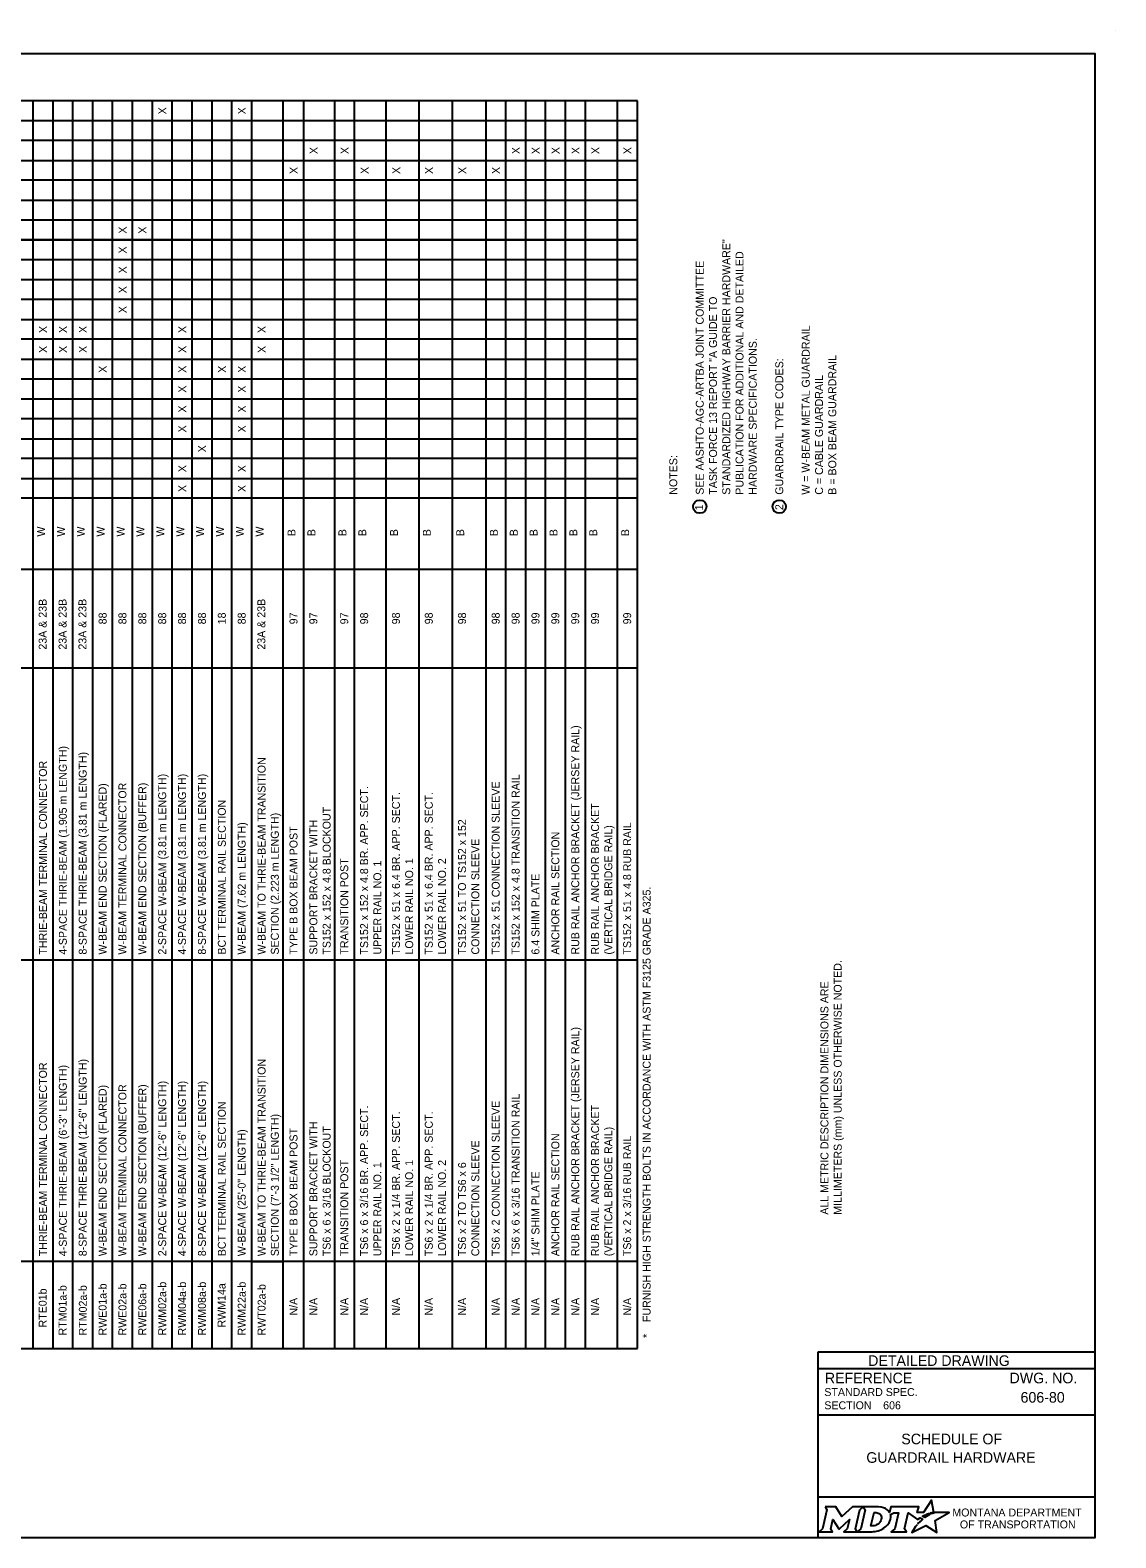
# Model space of a CAD drawing. Extents: x 49991.4 to 50021, y 49987.6 to 50011.4.
# Drawn here: x 50008.71 to 50016.9, y 49987.8 to 49999.18 of the extents above; entities that cross this region are included whole.
import ezdxf

# ---------------------------------------------------------------- set-up
doc = ezdxf.new("R2010")
doc.units = 0
for name, color, linetype in [('Default', 7, 'Continuous'), ('Level 1', 7, 'Continuous'), ('Level 2', 7, 'Continuous'), ('Level 5', 7, 'Continuous')]:
    doc.layers.add(name, color=color, linetype=linetype)

msp = doc.modelspace()

# ---------------------------------------------------------------- linework, layer by layer
at = {"layer": 'Default'}
for points in [[(50015.513, 49987.981), (50015.502, 49987.987), (50015.514, 49987.99), (50015.526, 49987.991), (50015.508, 49988.082), (50015.449, 49987.99), (50015.401, 49987.99), (50015.412, 49988.034), (50015.202, 49988.034), (50015.192, 49987.991), (50015.186, 49988)], [(50014.706, 49988.034), (50014.72, 49988.01), (50014.686, 49987.867), (50014.66, 49987.845), (50014.762, 49987.845), (50014.749, 49987.867), (50014.765, 49987.937), (50014.809, 49987.868), (50014.814, 49987.868), (50014.889, 49987.938), (50014.872, 49987.867), (50014.848, 49987.845), (50014.949, 49987.845), (50014.936, 49987.868), (50014.969, 49988.011)], [(50014.969, 49988.011), (50014.994, 49988.034), (50014.912, 49988.034), (50014.832, 49987.961), (50014.788, 49988.034), (50014.706, 49988.034)], [(50015.108, 49988.034), (50014.994, 49988.034), (50015.009, 49988.011), (50014.975, 49987.867), (50014.949, 49987.845), (50015.06, 49987.845)], [(50015.132, 49987.947), (50015.13, 49987.939), (50015.127, 49987.93), (50015.123, 49987.922), (50015.118, 49987.914), (50015.111, 49987.907), (50015.103, 49987.901), (50015.095, 49987.896), (50015.086, 49987.892), (50015.077, 49987.89), (50015.067, 49987.889), (50015.052, 49987.889), (50015.075, 49987.989), (50015.091, 49987.989), (50015.099, 49987.988), (50015.106, 49987.986), (50015.113, 49987.983), (50015.119, 49987.979), (50015.124, 49987.974), (50015.128, 49987.968), (50015.13, 49987.962), (50015.132, 49987.955), (50015.132, 49987.952), (50015.132, 49987.947)], [(50015.199, 49987.975), (50015.224, 49987.988), (50015.261, 49987.988), (50015.232, 49987.867), (50015.205, 49987.845), (50015.321, 49987.845), (50015.304, 49987.867), (50015.332, 49987.988), (50015.403, 49987.936), (50015.424, 49987.951), (50015.444, 49987.94)], [(50015.388, 49987.884), (50015.373, 49987.86), (50015.368, 49987.852), (50015.362, 49987.844), (50015.36, 49987.839), (50015.465, 49987.893), (50015.549, 49987.838), (50015.536, 49987.93), (50015.643, 49987.989), (50015.594, 49987.989), (50015.564, 49987.99), (50015.543, 49987.99), (50015.536, 49987.989), (50015.531, 49987.987), (50015.523, 49987.985), (50015.513, 49987.981)], [(50015.462, 49987.954), (50015.46, 49987.952), (50015.442, 49987.961), (50015.452, 49987.967), (50015.456, 49987.969), (50015.465, 49987.973), (50015.47, 49987.976), (50015.478, 49987.979), (50015.485, 49987.982), (50015.497, 49987.974), (50015.493, 49987.972), (50015.489, 49987.97), (50015.484, 49987.967), (50015.479, 49987.965), (50015.478, 49987.963), (50015.475, 49987.962), (50015.472, 49987.96), (50015.47, 49987.959), (50015.467, 49987.957), (50015.465, 49987.955), (50015.462, 49987.954)], [(50015.106, 49987.852), (50015.114, 49987.855), (50015.127, 49987.86), (50015.148, 49987.871)], [(50015.402, 49987.9), (50015.402, 49987.9)]]:
    msp.add_lwpolyline(points, dxfattribs=at)
for centre, radius, start, end in [((50015.087, 49987.973), 0.118, 300.9103, 339.1383), ((50015.131, 49987.955), 0.0709, 339.5329, 15.8582)]:
    msp.add_arc(centre, radius, start, end, dxfattribs=at)
for centre, major_axis, ratio, start_param, end_param in [((50015.106, 49987.986), (0.0834, -0.0037), 0.568097, 0.61298, 1.570796), ((50015.161, 49987.994), (0.0361, -0.0295), 0.469099, 1.225588, 1.570796), ((50015.433, 49987.93), (-0.0112, -0.0097), 0.021651, 3.157348, 6.283185), ((50015.06, 49987.993), (0, 0.148), 0.987302, 3.139398, 3.456847), ((50015.395, 49987.892), (-0.00694, -0.00806), 0.008222, 0, 3.137361), ((50015.412, 49987.911), (-0.0098, -0.0102), 0.016458, 3.141593, 6.279097)]:
    msp.add_ellipse(centre, major_axis=major_axis, ratio=ratio, start_param=start_param, end_param=end_param, dxfattribs=at)
at = {"layer": 'Level 1'}
msp.add_line((50016.9, 49999.176), (50016.9, 49999.176), dxfattribs=at)
msp.add_lwpolyline([(49999.375, 49998.999), (50016.742, 49998.999), (50016.742, 49987.799), (49999.375, 49987.799)], close=True, dxfattribs=at)
at = {"layer": 'Level 2'}
for p, q in [((50013.289, 49998.643), (49999.65, 49998.643)), ((50008.729, 49989.227), (50008.729, 49998.643)), ((50008.879, 49989.227), (50008.879, 49998.643)), ((50009.029, 49989.227), (50009.029, 49998.643)), ((50009.179, 49989.227), (50009.179, 49998.643)), ((50009.329, 49989.227), (50009.329, 49998.643)), ((50009.479, 49989.227), (50009.479, 49998.643)), ((50009.629, 49989.227), (50009.629, 49998.643)), ((50009.779, 49989.227), (50009.779, 49998.643)), ((50009.929, 49989.227), (50009.929, 49998.643)), ((50010.079, 49989.227), (50010.079, 49998.643)), ((50010.229, 49989.227), (50010.229, 49998.643)), ((50010.379, 49989.227), (50010.379, 49998.643)), ((50010.616, 49989.227), (50010.616, 49998.643)), ((50010.771, 49989.227), (50010.771, 49998.643)), ((50011.005, 49989.227), (50011.005, 49998.643)), ((50011.155, 49989.227), (50011.155, 49998.643)), ((50011.394, 49989.227), (50011.394, 49998.643)), ((50011.642, 49989.227), (50011.642, 49998.643)), ((50011.893, 49989.227), (50011.893, 49998.643)), ((50012.147, 49989.227), (50012.147, 49998.643)), ((50012.297, 49989.227), (50012.297, 49998.643)), ((50012.447, 49989.227), (50012.447, 49998.643)), ((50012.597, 49989.227), (50012.597, 49998.643)), ((50012.747, 49989.227), (50012.747, 49998.643)), ((50012.897, 49989.227), (50012.897, 49998.643)), ((50013.139, 49989.227), (50013.139, 49998.643)), ((50013.289, 49989.227), (50013.289, 49998.643)), ((49999.85, 49998.493), (50013.289, 49998.493)), ((49999.85, 49998.193), (50013.289, 49998.193)), ((50013.289, 49998.043), (49999.85, 49998.043)), ((49999.85, 49997.893), (50013.289, 49997.893)), ((50013.289, 49997.743), (49999.85, 49997.743)), ((49999.85, 49997.593), (50013.289, 49997.593)), ((50013.289, 49997.593), (49999.85, 49997.593)), ((49999.85, 49997.593), (50013.289, 49997.593)), ((50013.289, 49997.443), (49999.85, 49997.443)), ((49999.85, 49997.293), (50013.289, 49997.293)), ((50013.289, 49997.143), (49999.85, 49997.143)), ((49999.85, 49996.993), (50013.289, 49996.993)), ((50013.289, 49996.843), (49999.85, 49996.843)), ((49999.85, 49996.693), (50013.289, 49996.693)), ((50013.289, 49996.543), (49999.85, 49996.543)), ((49999.85, 49996.393), (50013.289, 49996.393)), ((50013.289, 49996.243), (49999.85, 49996.243)), ((49999.85, 49996.093), (50013.289, 49996.093)), ((50013.289, 49995.943), (49999.85, 49995.943)), ((49999.85, 49995.793), (50013.289, 49995.793)), ((50013.289, 49995.643), (49999.65, 49995.643)), ((50000.05, 49995.108), (50013.289, 49995.108)), ((50013.289, 49994.362), (50000.05, 49994.362)), ((50000.05, 49992.16), (50013.289, 49992.16)), ((50013.289, 49989.884), (50000.05, 49989.884)), ((50010.379, 49989.884), (50010.616, 49989.884)), ((49999.85, 49989.227), (50013.289, 49989.227))]:
    msp.add_line(p, q, dxfattribs=at)
msp.add_lwpolyline([(50013.289, 49998.343), (49999.85, 49998.343)], dxfattribs=at)
for centre in [(50013.76, 49995.58), (50014.36, 49995.58)]:
    msp.add_circle(centre, 0.05, dxfattribs=at)
at = {"layer": 'Level 5'}
for p, q in [((50016.75, 49989.199), (50014.65, 49989.199)), ((50014.65, 49989.199), (50014.65, 49987.799)), ((50016.75, 49989.074), (50014.65, 49989.074)), ((50016.386, 49988.859), (50016.386, 49988.859)), ((50016.75, 49988.724), (50014.65, 49988.724)), ((50015.144, 49988.799), (50015.144, 49988.799)), ((50015.7, 49988.475), (50015.7, 49988.475)), ((50016.75, 49988.106), (50014.65, 49988.106))]:
    msp.add_line(p, q, dxfattribs=at)

# ---------------------------------------------------------------- texts
at = {"layer": 'Default'}
for s, p in [('MONTANA DEPARTMENT', (50015.666, 49987.96)), ('OF TRANSPORTATION', (50015.723, 49987.87))]:
    msp.add_text(s, height=0.06, dxfattribs=at).set_placement(p)
at = {"layer": 'Level 2'}
for s, p in [('X', (50009.734, 49998.54)), ('X', (50010.334, 49998.54)), ('X', (50010.876, 49998.24)), ('X', (50011.11, 49998.24)), ('X', (50012.402, 49998.24)), ('X', (50012.552, 49998.24)), ('X', (50012.702, 49998.24)), ('X', (50012.852, 49998.24)), ('X', (50013.002, 49998.24)), ('X', (50013.244, 49998.24)), ('X', (50010.726, 49998.09)), ('X', (50011.26, 49998.09)), ('X', (50011.499, 49998.09)), ('X', (50011.747, 49998.09)), ('X', (50011.998, 49998.09)), ('X', (50012.252, 49998.09)), ('X', (50009.434, 49997.64)), ('X', (50009.584, 49997.64)), ('X', (50009.434, 49997.49)), ('STANDARDIZED HIGHWAY BARRIER HARDWARE"', (50013.99, 49995.67)), ('PUBLICATION FOR ADDITIONAL AND DETAILED', (50014.09, 49995.67)), ('X', (50009.434, 49997.34)), ('SEE AASHTO-AGC-ARTBA JOINT COMMITTEE', (50013.79, 49995.67)), ('X', (50009.434, 49997.19)), ('TASK FORCE 13 REPORT "A GUIDE TO', (50013.89, 49995.67)), ('X', (50009.434, 49997.04)), ('X', (50008.834, 49996.89)), ('X', (50008.984, 49996.89)), ('X', (50009.134, 49996.89)), ('X', (50009.884, 49996.89)), ('X', (50010.484, 49996.89)), ('W = W-BEAM METAL GUARDRAIL', (50014.59, 49995.67)), ('HARDWARE SPECIFICATIONS.', (50014.19, 49995.67)), ('X', (50008.834, 49996.74)), ('X', (50008.984, 49996.74)), ('X', (50009.134, 49996.74)), ('X', (50009.884, 49996.74)), ('X', (50010.484, 49996.74)), ('GUARDRAIL TYPE CODES:', (50014.39, 49995.67)), ('B = BOX BEAM GUARDRAIL', (50014.79, 49995.67)), ('X', (50009.284, 49996.59)), ('X', (50009.884, 49996.59)), ('X', (50010.184, 49996.59)), ('X', (50010.334, 49996.59)), ('X', (50009.884, 49996.44)), ('X', (50010.334, 49996.44)), ('C = CABLE GUARDRAIL', (50014.69, 49995.67)), ('X', (50009.884, 49996.29)), ('X', (50010.334, 49996.29)), ('X', (50009.884, 49996.14)), ('X', (50010.334, 49996.14)), ('X', (50010.034, 49995.99)), ('X', (50009.884, 49995.84)), ('X', (50010.334, 49995.84)), ('NOTES:', (50013.59, 49995.67)), ('X', (50009.884, 49995.69)), ('X', (50010.334, 49995.69)), ('1', (50013.785, 49995.552)), ('2', (50014.39, 49995.554)), ('W', (50008.819, 49995.354)), ('W', (50008.969, 49995.354)), ('W', (50009.119, 49995.354)), ('W', (50009.269, 49995.354)), ('W', (50009.419, 49995.354)), ('W', (50009.569, 49995.354)), ('W', (50009.719, 49995.354)), ('W', (50009.869, 49995.354)), ('W', (50010.019, 49995.354)), ('W', (50010.169, 49995.354)), ('W', (50010.319, 49995.354)), ('W', (50010.469, 49995.354)), ('B', (50010.709, 49995.357)), ('B', (50010.859, 49995.357)), ('B', (50011.093, 49995.357)), ('B', (50011.243, 49995.357)), ('B', (50011.482, 49995.357)), ('B', (50011.73, 49995.357)), ('B', (50011.982, 49995.357)), ('B', (50012.236, 49995.357)), ('B', (50012.386, 49995.357)), ('B', (50012.536, 49995.357)), ('B', (50012.686, 49995.357)), ('B', (50012.836, 49995.357)), ('B', (50012.986, 49995.357)), ('B', (50013.227, 49995.357)), ('23A & 23B', (50008.831, 49994.501)), ('23A & 23B', (50008.981, 49994.501)), ('23A & 23B', (50009.131, 49994.501)), ('23A & 23B', (50010.481, 49994.501)), ('88', (50009.283, 49994.692)), ('88', (50009.433, 49994.692)), ('88', (50009.583, 49994.692)), ('88', (50009.733, 49994.692)), ('88', (50009.883, 49994.692)), ('88', (50010.033, 49994.692)), ('18', (50010.183, 49994.692)), ('88', (50010.333, 49994.692)), ('97', (50010.724, 49994.692)), ('97', (50010.874, 49994.692)), ('97', (50011.107, 49994.692)), ('98', (50011.257, 49994.692)), ('98', (50011.497, 49994.692)), ('98', (50011.745, 49994.692)), ('98', (50011.996, 49994.692)), ('98', (50012.25, 49994.692)), ('98', (50012.4, 49994.692)), ('99', (50012.55, 49994.692)), ('99', (50012.7, 49994.692)), ('99', (50012.85, 49994.692)), ('99', (50013, 49994.692)), ('99', (50013.242, 49994.692)), ('RUB RAIL ANCHOR BRACKET (JERSEY RAIL)', (50012.85, 49992.2)), ('4-SPACE THRIE-BEAM (1.905 m LENGTH)', (50008.983, 49992.2)), ('THRIE-BEAM TERMINAL CONNECTOR', (50008.833, 49992.2)), ('8-SPACE THRIE-BEAM (3.81 m LENGTH)', (50009.133, 49992.2)), ('W-BEAM TO THRIE-BEAM TRANSITION', (50010.483, 49992.2)), ('2-SPACE W-BEAM (3.81 m LENGTH)', (50009.733, 49992.2)), ('4-SPACE W-BEAM (3.81 m LENGTH)', (50009.883, 49992.2)), ('8-SPACE W-BEAM (3.81 m LENGTH)', (50010.033, 49992.2)), ('TS152 x 51 CONNECTION SLEEVE', (50012.25, 49992.2)), ('TS152 x 152 x 4.8 TRANSITION RAIL', (50012.4, 49992.2)), ('W-BEAM END SECTION (FLARED)', (50009.283, 49992.2)), ('W-BEAM TERMINAL CONNECTOR', (50009.433, 49992.2)), ('W-BEAM END SECTION (BUFFER)', (50009.583, 49992.2)), ('TS152 x 152 x 4.8 BR. APP. SECT.', (50011.257, 49992.2)), ('TS152 x 51 x 6.4 BR. APP. SECT.', (50011.497, 49992.2)), ('TS152 x 51 x 6.4 BR. APP. SECT.', (50011.745, 49992.2)), ('BCT TERMINAL RAIL SECTION', (50010.183, 49992.2)), ('TS152 x 152 x 4.8 BLOCKOUT', (50010.974, 49992.2)), ('RUB RAIL ANCHOR BRACKET', (50013, 49992.2)), ('W-BEAM (7.62 m LENGTH)', (50010.333, 49992.2)), ('SECTION (2.223 m LENGTH)', (50010.583, 49992.2)), ('TYPE B BOX BEAM POST', (50010.724, 49992.2)), ('SUPPORT BRACKET WITH', (50010.874, 49992.2)), ('TS152 x 51 TO TS152 x 152', (50011.996, 49992.2)), ('(VERTICAL BRIDGE RAIL)', (50013.1, 49992.2)), ('TS152 x 51 x 4.8 RUB RAIL', (50013.242, 49992.2)), ('CONNECTION SLEEVE', (50012.096, 49992.2)), ('ANCHOR RAIL SECTION', (50012.7, 49992.2)), ('TRANSITION POST', (50011.107, 49992.2)), ('UPPER RAIL NO. 1', (50011.357, 49992.2)), ('LOWER RAIL NO. 1', (50011.597, 49992.2)), ('LOWER RAIL NO. 2', (50011.845, 49992.2)), ('6.4 SHIM PLATE', (50012.55, 49992.2)), ('FURNISH HIGH STRENGTH BOLTS IN ACCORDANCE WITH ASTM F3125 GRADE A325.', (50013.389, 49989.427)), ('MILLIMETERS (mm) UNLESS OTHERWISE NOTED.', (50014.831, 49990.237)), ('ALL METRIC DESCRIPTION DIMENSIONS ARE', (50014.731, 49990.237)), ('RUB RAIL ANCHOR BRACKET (JERSEY RAIL)', (50012.85, 49989.924)), ('THRIE-BEAM TERMINAL CONNECTOR', (50008.833, 49989.924)), ('4-SPACE THRIE-BEAM (6\'-3" LENGTH)', (50008.983, 49989.924)), ('8-SPACE THRIE-BEAM (12\'-6" LENGTH)', (50009.133, 49989.924)), ('W-BEAM TO THRIE-BEAM TRANSITION', (50010.483, 49989.924)), ('2-SPACE W-BEAM (12\'-6" LENGTH)', (50009.733, 49989.924)), ('4-SPACE W-BEAM (12\'-6" LENGTH)', (50009.883, 49989.924)), ('8-SPACE W-BEAM (12\'-6" LENGTH)', (50010.033, 49989.924)), ('W-BEAM END SECTION (FLARED)', (50009.283, 49989.924)), ('W-BEAM TERMINAL CONNECTOR', (50009.433, 49989.924)), ('W-BEAM END SECTION (BUFFER)', (50009.583, 49989.924)), ('TS6 x 6 x 3/16 TRANSITION RAIL', (50012.4, 49989.924)), ('BCT TERMINAL RAIL SECTION', (50010.183, 49989.924)), ('TS6 x 6 x 3/16 BR. APP. SECT.', (50011.257, 49989.924)), ('TS6 x 2 x 1/4 BR. APP. SECT.', (50011.497, 49989.924)), ('TS6 x 2 x 1/4 BR. APP. SECT.', (50011.745, 49989.924)), ('TS6 x 2 CONNECTION SLEEVE', (50012.25, 49989.924)), ('RUB RAIL ANCHOR BRACKET', (50013, 49989.924)), ('SECTION (7\'-3 1/2" LENGTH)', (50010.583, 49989.924)), ('TYPE B BOX BEAM POST', (50010.724, 49989.924)), ('SUPPORT BRACKET WITH', (50010.874, 49989.924)), ('TS6 x 6 x 3/16 BLOCKOUT', (50010.974, 49989.924)), ('(VERTICAL BRIDGE RAIL)', (50013.1, 49989.924)), ('W-BEAM (25\'-0" LENGTH)', (50010.333, 49989.924)), ('CONNECTION SLEEVE', (50012.096, 49989.924)), ('ANCHOR RAIL SECTION', (50012.7, 49989.924)), ('TS6 x 2 x 3/16 RUB RAIL', (50013.242, 49989.924)), ('TRANSITION POST', (50011.107, 49989.924)), ('UPPER RAIL NO. 1', (50011.357, 49989.924)), ('LOWER RAIL NO. 1', (50011.597, 49989.924)), ('LOWER RAIL NO. 2', (50011.845, 49989.924)), ('TS6 x 2 TO TS6 x 6', (50011.996, 49989.924)), ('1/4" SHIM PLATE', (50012.55, 49989.924)), ('RTE01b', (50008.831, 49989.386)), ('RTM01a-b', (50008.981, 49989.326)), ('RTM02a-b', (50009.134, 49989.326)), ('RWE01a-b', (50009.283, 49989.326)), ('RWE02a-b', (50009.433, 49989.326)), ('RWE06a-b', (50009.583, 49989.326)), ('RWM02a-b', (50009.733, 49989.326)), ('RWM04a-b', (50009.883, 49989.326)), ('RWM08a-b', (50010.033, 49989.326)), ('RWM14a', (50010.181, 49989.386)), ('RWM22a-b', (50010.333, 49989.326)), ('RWT02a-b', (50010.483, 49989.326)), ('N/A', (50010.724, 49989.476)), ('N/A', (50010.874, 49989.476)), ('N/A', (50011.107, 49989.476)), ('N/A', (50011.257, 49989.476)), ('N/A', (50011.497, 49989.476)), ('N/A', (50011.745, 49989.476)), ('N/A', (50011.996, 49989.476)), ('N/A', (50012.25, 49989.476)), ('N/A', (50012.4, 49989.476)), ('N/A', (50012.55, 49989.476)), ('N/A', (50012.7, 49989.476)), ('N/A', (50012.85, 49989.476)), ('N/A', (50013, 49989.476)), ('N/A', (50013.242, 49989.476)), ('*', (50013.389, 49989.307))]:
    msp.add_text(s, height=0.06, rotation=90, dxfattribs=at).set_placement(p)
for s, height, p in [('606-80', 0.08, (50016.181, 49988.819)), ('606', 0.06, (50015.144, 49988.769)), ('SCHEDULE OF', 0.08, (50015.281, 49988.505)), ('GUARDRAIL HARDWARE', 0.08, (50015.017, 49988.365))]:
    msp.add_text(s, height=height, dxfattribs=at).set_placement(p)
at = {"layer": 'Level 5'}
for s, height, p in [('DETAILED DRAWING', 0.0799, (50015.031, 49989.096)), ('REFERENCE', 0.08, (50014.704, 49988.965)), ('DWG. NO.', 0.08, (50016.098, 49988.965)), ('STANDARD SPEC.', 0.06, (50014.7, 49988.869)), ('SECTION', 0.06, (50014.7, 49988.769))]:
    msp.add_text(s, height=height, dxfattribs=at).set_placement(p)

doc.saveas('drawing.dxf')
